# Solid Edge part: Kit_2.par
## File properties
Dokumentum tartalom típus: 0
Last saved by: ahadarics
Revision: 77
Sűrűség: 0,000 kg/m^3
Pontosság: 0,990
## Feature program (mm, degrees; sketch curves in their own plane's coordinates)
base feature "unnamed BaseFeature 1"
sketch for "unnamed Hole 1" plane through (-19, 19, 5) normal (0, 0, -1) x-axis (0, -1, 0)
hole "unnamed Hole 1" through
sketch for "unnamed Hole 2" plane through (-19, 19, 5) normal (0, 0, -1) x-axis (0, -1, 0)
  hole centre (38, 0) bore radius 2.4585
hole "unnamed Hole 2" through
sketch for "unnamed Hole 3" plane through (-19, 19, 5) normal (0, 0, -1) x-axis (0, -1, 0)
  hole centre (38, -38) bore radius 2.4585
hole "unnamed Hole 3" through
sketch for "unnamed Hole 4" plane through (-19, 19, 5) normal (0, 0, -1) x-axis (0, -1, 0)
  hole centre (0, -38) bore radius 2.4585
hole "unnamed Hole 4" through
pattern "unnamed Pattern 1" of "unnamed Hole 1", "unnamed Hole 2", "unnamed Hole 3", "unnamed Hole 4"
sketch for "Furat_5" plane through (-26.4338, 0.0026, 8.0029) normal (-0.999944, 0, -0.01058) x-axis (0.01058, 0, -0.999944)
  hole centre (0.0048, 0.0031) bore radius 4.283
hole "Furat_5" diameter 8.566 finite
thread "unnamed Thread 1"
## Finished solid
Body 1: solid body, 289 faces, 687 edges, 418 vertices, 4 internal voids.
  Faces by surface: plane 145, cylinder 71, swept 43, torus 20, cone 9, spline 1
  Edges by curve: line 415, circle 158, spline 98, ellipse 12, curve on surface 4
Bounding box of the edges (mm; curved faces can reach further): 54.800 x 54.800 x 14.500, from (-27.4, -27.4, 0) to (27.4, 27.4, 14.5).
Cylindrical faces by radius (mm): R0.2 x36, R0.519 x1, R2.4585 x4, R2.5402 x12, R2.6 x4, R3.75 x4, R3.85 x4, R4.283 x1, R4.5 x5
Conical faces (half-angle, radius in mm at the cone's reference point): 0.5 deg R6.75 x4, 45 deg R2.7085 x4, 45 deg R4.65 x1
Toroidal faces (ring radius, tube radius in mm): R2.9402 r0.4 x12, R3.55 r0.2 x8
Planar faces by outward normal: +x 12, +y 15, +z 1, -x 13, -y 14, -z 22, oblique 68
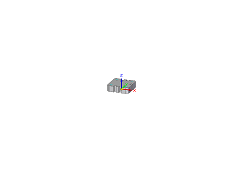
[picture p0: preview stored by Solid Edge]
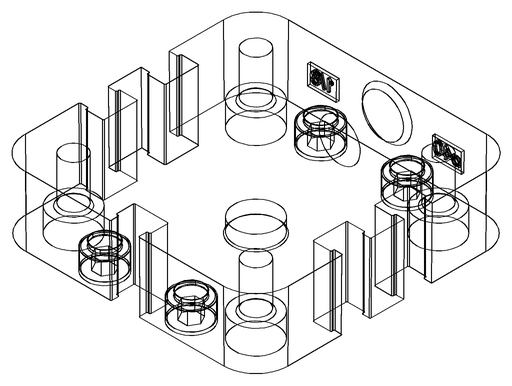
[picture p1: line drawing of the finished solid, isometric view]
